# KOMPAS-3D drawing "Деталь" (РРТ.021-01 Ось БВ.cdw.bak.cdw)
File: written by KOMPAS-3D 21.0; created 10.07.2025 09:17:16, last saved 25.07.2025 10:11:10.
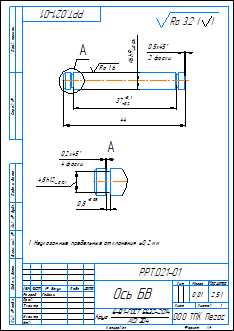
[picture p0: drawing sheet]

Sheet 1: A4, portrait

Document properties: Автор: User; Полное имя файла: C:\Users\User\Desktop\Ручной ротатор КД\Чертежи\РРТ.021-01 Ось БВ.cdw.bak.cdw; Знак неуказанной шероховатости: 4; Параметр неуказанной шероховатости: Ra 3.2; Масса: 0.009599

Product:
- Part/product: Деталь
    Масса: 0.009599
    Форматы листов документа: A4

Title block, sheet 1: Наименование: Ось БВ; designation: РРТ.021-01; Материал: Круг  6-B1-ГОСТ 5632-2014 AISI 304; Масса: 0,01; Количество листов документа: 1; organisation: ООО ТПК Пегас; Форматы листов документа: A4; stored path: C:\Users\User\Desktop\Р-й Рот-р\Компас чертежи\Ось хомута ПРС.cdw; Разработал: Гайсин

Views: Вид 1, Слева, Выносной элемент 2, Выносной элемент А, Выносной элемент
Referenced files in C:\Users\User\Desktop\Ручной ротатор Ринат\П2\: Ось ПРС.m3d
Referenced files in C:\Users\User\Desktop\Ручной ротатор КД\Модели КД\: РРТ.021-01 Ось БВ.m3d
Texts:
  Ra 1.6
  Ra 3.2
  Ra 3.2 ( )
Dimensions and other numbers on the sheet: 6; 44; 0,5; 2 фаски; 37; 4,8; 0,2; 4 фаски; 0,8; 2,5:1; 1; 0,01

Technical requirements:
  Неуказанные предельные отклонения  0,2 мм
